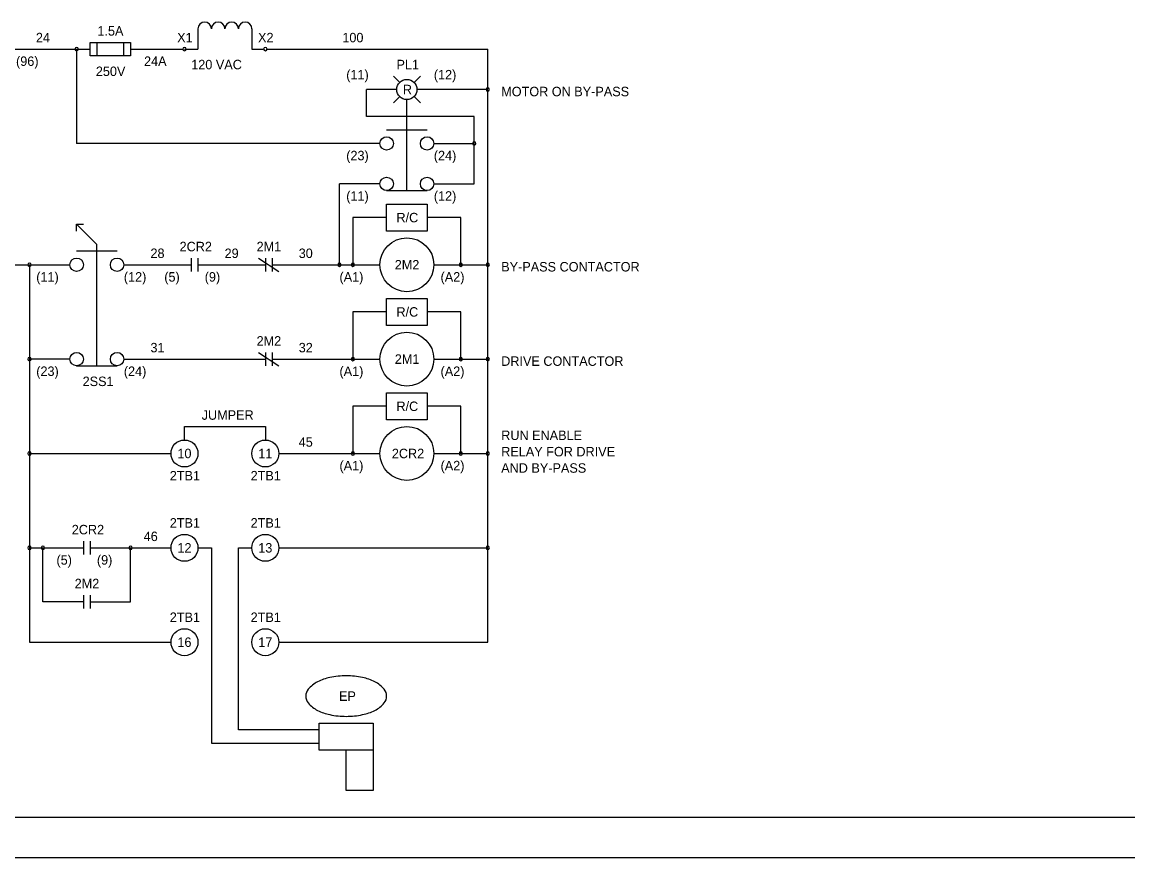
# Model space of a CAD drawing. Extents: x 10338 to 10578, y 10012 to 10165.
# Drawn here: x 10403.8 to 10481.8, y 10064.7 to 10123.6 of the extents above; entities that cross this region are included whole.
import ezdxf

# ---------------------------------------------------------------- set-up
doc = ezdxf.new("R2010")
doc.units = 0
for name, color, linetype in [('Level 61', 7, 'Continuous'), ('Level 62', 7, 'Continuous'), ('Level 63', 7, 'Continuous')]:
    doc.layers.add(name, color=color, linetype=linetype)

# ---------------------------------------------------------------- blocks, each defined once
blk = doc.blocks.new('PL0')
at = {"layer": 'Level 63'}
for p, q in [((-0.00552, 0.00552), (-0.01042, 0.01042)), ((0.00552, 0.00552), (0.01042, 0.01042)), ((-0.00552, -0.00552), (-0.01042, -0.01042)), ((0.00552, -0.00552), (0.01042, -0.01042))]:
    blk.add_line(p, q, dxfattribs=at)
blk.add_circle((0, 0), 0.00781, dxfattribs=at)
blk = doc.blocks.new('EL0')
at = {"layer": 'Level 63'}
for centre, radius, start, end in [((-0.01206, -0.00902), 0.02244, 116.56505, 140.36073), ((-0.00479, -0.02357), 0.0387, 101.70092, 116.56505), ((0, -0.04669), 0.06232, 90, 101.70092), ((0, -0.04669), 0.06232, 78.29908, 90), ((0.00479, -0.02357), 0.0387, 63.43495, 78.29908), ((0.01206, -0.00902), 0.02244, 39.63927, 63.43495), ((-0.02295, 0), 0.0083, 140.36073, 180), ((-0.02295, 0), 0.0083, 180, 219.63927), ((0.02295, 0), 0.0083, 0, 39.63927), ((0.02295, 0), 0.0083, 320.36073, 0), ((-0.01206, 0.00902), 0.02244, 219.63927, 243.43495), ((0.01206, 0.00902), 0.02244, 296.56505, 320.36073), ((-0.00479, 0.02357), 0.0387, 243.43495, 258.29908), ((0, 0.04669), 0.06232, 258.29908, 270), ((0, 0.04669), 0.06232, 270, 281.70092), ((0.00479, 0.02357), 0.0387, 281.70092, 296.56505)]:
    blk.add_arc(centre, radius, start, end, dxfattribs=at)

msp = doc.modelspace()

# ---------------------------------------------------------------- linework, layer by layer
at = {"layer": 'Level 61'}
for p, q in [((10409.092, 10122.19), (10409.092, 10121.24)), ((10410.992, 10121.24), (10410.992, 10122.19)), ((10402.917, 10121.715), (10408.617, 10121.715)), ((10407.667, 10121.715), (10407.667, 10115.065)), ((10411.467, 10121.715), (10415.148, 10121.715)), ((10421.086, 10121.715), (10436.642, 10121.715)), ((10436.642, 10079.915), (10436.642, 10121.715)), ((10430.229, 10118.865), (10428.092, 10118.865)), ((10428.092, 10116.965), (10428.092, 10118.865)), ((10436.642, 10118.865), (10431.654, 10118.865)), ((10430.942, 10111.74), (10430.942, 10118.153)), ((10435.692, 10116.965), (10428.092, 10116.965)), ((10435.692, 10112.215), (10435.692, 10116.965)), ((10429.042, 10115.065), (10407.667, 10115.065)), ((10432.842, 10115.065), (10435.692, 10115.065)), ((10426.192, 10106.515), (10426.192, 10112.215)), ((10429.042, 10112.215), (10426.192, 10112.215)), ((10432.842, 10112.215), (10435.692, 10112.215)), ((10427.142, 10109.84), (10427.142, 10106.515)), ((10429.517, 10109.84), (10427.142, 10109.84)), ((10434.742, 10109.84), (10432.367, 10109.84)), ((10434.742, 10106.515), (10434.742, 10109.84)), ((10409.092, 10099.39), (10409.092, 10107.94)), ((10400.542, 10106.515), (10407.192, 10106.515)), ((10404.342, 10106.515), (10404.342, 10079.915)), ((10410.992, 10106.515), (10415.742, 10106.515)), ((10416.217, 10106.515), (10420.967, 10106.515)), ((10420.492, 10106.99), (10421.917, 10106.04)), ((10421.442, 10106.515), (10429.042, 10106.515)), ((10432.842, 10106.515), (10436.642, 10106.515)), ((10427.142, 10103.19), (10427.142, 10099.865)), ((10429.517, 10103.19), (10427.142, 10103.19)), ((10434.742, 10103.19), (10432.367, 10103.19)), ((10434.742, 10099.865), (10434.742, 10103.19)), ((10420.492, 10100.34), (10421.917, 10099.39)), ((10407.192, 10099.865), (10404.342, 10099.865)), ((10410.992, 10099.865), (10420.967, 10099.865)), ((10421.442, 10099.865), (10429.042, 10099.865)), ((10432.842, 10099.865), (10436.642, 10099.865)), ((10427.142, 10096.54), (10427.142, 10093.215)), ((10429.517, 10096.54), (10427.142, 10096.54)), ((10434.742, 10096.54), (10432.367, 10096.54)), ((10434.742, 10093.215), (10434.742, 10096.54)), ((10404.342, 10093.215), (10414.317, 10093.215)), ((10421.917, 10093.215), (10429.042, 10093.215)), ((10432.842, 10093.215), (10436.642, 10093.215)), ((10404.342, 10086.565), (10408.142, 10086.565)), ((10405.292, 10082.765), (10405.292, 10086.565)), ((10408.617, 10086.565), (10414.317, 10086.565)), ((10411.467, 10082.765), (10411.467, 10086.565)), ((10416.217, 10086.565), (10417.167, 10086.565)), ((10417.167, 10086.565), (10417.167, 10072.79)), ((10419.067, 10073.74), (10419.067, 10086.565)), ((10419.067, 10086.565), (10420.017, 10086.565)), ((10421.917, 10086.565), (10436.642, 10086.565)), ((10408.142, 10082.765), (10405.292, 10082.765)), ((10408.617, 10082.765), (10411.467, 10082.765)), ((10404.342, 10079.915), (10414.317, 10079.915)), ((10421.917, 10079.915), (10436.642, 10079.915)), ((10424.767, 10073.74), (10419.067, 10073.74)), ((10417.167, 10072.79), (10424.767, 10072.79)), ((10521.192, 10067.565), (10376.317, 10067.565)), ((10524.042, 10064.715), (10373.467, 10064.715))]:
    msp.add_line(p, q, dxfattribs=at)
msp.add_lwpolyline([(10415.267, 10094.165), (10415.267, 10095.115), (10420.967, 10095.115), (10420.967, 10094.165)], dxfattribs=at)
for centre, start, end in [((10407.667, 10121.715), 0, 180), ((10407.667, 10121.715), 180, 0), ((10436.642, 10118.865), 0, 180), ((10436.642, 10118.865), 180, 0), ((10435.692, 10115.065), 0, 180), ((10435.692, 10115.065), 180, 0), ((10404.342, 10106.515), 0, 180), ((10404.342, 10106.515), 180, 0), ((10426.192, 10106.515), 0, 180), ((10426.192, 10106.515), 180, 0), ((10427.142, 10106.515), 0, 180), ((10427.142, 10106.515), 180, 0), ((10434.742, 10106.515), 0, 180), ((10434.742, 10106.515), 180, 0), ((10436.642, 10106.515), 0, 180), ((10436.642, 10106.515), 180, 0), ((10404.342, 10099.865), 0, 180), ((10404.342, 10099.865), 180, 0), ((10427.142, 10099.865), 0, 180), ((10427.142, 10099.865), 180, 0), ((10434.742, 10099.865), 0, 180), ((10434.742, 10099.865), 180, 0), ((10436.642, 10099.865), 0, 180), ((10436.642, 10099.865), 180, 0), ((10404.342, 10093.215), 0, 180), ((10404.342, 10093.215), 180, 0), ((10427.142, 10093.215), 0, 180), ((10427.142, 10093.215), 180, 0), ((10434.742, 10093.215), 0, 180), ((10434.742, 10093.215), 180, 0), ((10436.642, 10093.215), 0, 180), ((10436.642, 10093.215), 180, 0), ((10404.342, 10086.565), 0, 180), ((10404.342, 10086.565), 180, 0), ((10405.292, 10086.565), 0, 180), ((10405.292, 10086.565), 180, 0), ((10411.467, 10086.565), 0, 180), ((10411.467, 10086.565), 180, 0), ((10436.642, 10086.565), 0, 180), ((10436.642, 10086.565), 180, 0)]:
    msp.add_arc(centre, 0.119, start, end, dxfattribs=at)
at = {"layer": 'Level 62'}
for p, q in [((10416.217, 10123.14), (10416.217, 10121.715)), ((10420.017, 10123.14), (10420.017, 10121.715)), ((10415.267, 10121.715), (10416.217, 10121.715)), ((10420.017, 10121.715), (10420.808, 10121.715)), ((10429.517, 10116.015), (10432.367, 10116.015)), ((10429.517, 10111.74), (10432.367, 10111.74)), ((10409.092, 10107.94), (10407.667, 10109.365)), ((10407.667, 10108.89), (10407.667, 10109.365)), ((10407.667, 10109.365), (10408.142, 10109.365)), ((10410.517, 10107.465), (10407.667, 10107.465)), ((10415.742, 10106.99), (10415.742, 10106.04)), ((10416.217, 10106.99), (10416.217, 10106.04)), ((10420.967, 10106.99), (10420.967, 10106.04)), ((10421.442, 10106.99), (10421.442, 10106.04)), ((10420.967, 10100.34), (10420.967, 10099.39)), ((10421.442, 10100.34), (10421.442, 10099.39)), ((10407.667, 10099.39), (10410.517, 10099.39)), ((10408.142, 10087.04), (10408.142, 10086.09)), ((10408.617, 10087.04), (10408.617, 10086.09)), ((10408.142, 10083.24), (10408.142, 10082.29)), ((10408.617, 10083.24), (10408.617, 10082.29)), ((10424.767, 10072.315), (10424.767, 10074.215)), ((10424.767, 10074.215), (10428.567, 10074.215)), ((10428.567, 10074.215), (10428.567, 10069.465)), ((10428.567, 10072.315), (10424.767, 10072.315)), ((10426.667, 10069.465), (10426.667, 10072.315)), ((10428.567, 10069.465), (10426.667, 10069.465))]:
    msp.add_line(p, q, dxfattribs=at)
for points in [[(10408.617, 10122.19), (10411.467, 10122.19), (10411.467, 10121.24), (10408.617, 10121.24)], [(10429.517, 10110.79), (10432.367, 10110.79), (10432.367, 10108.89), (10429.517, 10108.89)], [(10429.517, 10104.14), (10432.367, 10104.14), (10432.367, 10102.24), (10429.517, 10102.24)], [(10429.517, 10097.49), (10432.367, 10097.49), (10432.367, 10095.59), (10429.517, 10095.59)]]:
    msp.add_lwpolyline(points, close=True, dxfattribs=at)
for centre, radius in [((10429.517, 10115.065), 0.475), ((10432.367, 10115.065), 0.475), ((10429.517, 10112.215), 0.475), ((10432.367, 10112.215), 0.475), ((10430.942, 10106.515), 1.9), ((10407.667, 10106.515), 0.475), ((10410.517, 10106.515), 0.475), ((10430.942, 10099.865), 1.9), ((10407.667, 10099.865), 0.475), ((10410.517, 10099.865), 0.475), ((10430.942, 10093.215), 1.9), ((10415.267, 10093.215), 0.95), ((10420.967, 10093.215), 0.95), ((10415.267, 10086.565), 0.95), ((10420.967, 10086.565), 0.95), ((10415.267, 10079.915), 0.95), ((10420.967, 10079.915), 0.95)]:
    msp.add_circle(centre, radius, dxfattribs=at)
for centre, radius, start, end in [((10416.692, 10123.14), 0.475, 0, 180), ((10417.642, 10123.14), 0.475, 0, 180), ((10418.592, 10123.14), 0.475, 0, 180), ((10419.542, 10123.14), 0.475, 0, 180), ((10415.267, 10121.715), 0.119, 0, 180), ((10415.267, 10121.715), 0.119, 180, 0), ((10420.967, 10121.715), 0.119, 0, 180), ((10420.967, 10121.715), 0.119, 180, 0)]:
    msp.add_arc(centre, radius, start, end, dxfattribs=at)

# ---------------------------------------------------------------- block references
at = {"layer": 'Level 62', "xscale": 91.19999999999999, "yscale": 91.2}
msp.add_blockref('PL0', (10430.943, 10118.866), dxfattribs=at)
at = {"layer": 'Level 63', "xscale": 91.19999999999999, "yscale": 91.2}
msp.add_blockref('EL0', (10426.668, 10076.116), dxfattribs=at)

# ---------------------------------------------------------------- texts
at = {"layer": 'Level 63'}
for s, height, p in [('24', 0.6667, (10404.794, 10122.191)), ('1.5A', 0.6667, (10409.129, 10122.666)), ('X1', 0.6667, (10414.752, 10122.191)), ('X2', 0.6667, (10420.453, 10122.191)), ('100', 0.6667, (10426.393, 10122.191)), ('(96)', 0.6667, (10403.393, 10120.528)), ('24A', 0.6667, (10412.418, 10120.528)), ('250V', 0.6667, (10409.019, 10119.816)), ('120 VAC', 0.6667, (10415.743, 10120.291)), ('PL1', 0.6667, (10430.212, 10120.291)), ('(11)', 0.6667, (10426.668, 10119.578)), ('(12)', 0.6667, (10432.843, 10119.578)), ('R', 0.667, (10430.659, 10118.532)), ('MOTOR ON BY-PASS', 0.66667, (10437.593, 10118.391)), ('(23)', 0.6667, (10426.668, 10113.878)), ('(24)', 0.6667, (10432.843, 10113.878)), ('(11)', 0.6667, (10426.668, 10111.028)), ('(12)', 0.6667, (10432.843, 10111.028)), ('R/C', 0.6667, (10430.208, 10109.507)), ('2CR2', 0.6667, (10414.922, 10107.466)), ('2M1', 0.6667, (10420.352, 10107.466)), ('28', 0.6667, (10412.869, 10106.991)), ('29', 0.6667, (10418.094, 10106.991)), ('30', 0.6667, (10423.318, 10106.991)), ('2M2', 0.6667, (10430.089, 10106.182)), ('BY-PASS CONTACTOR', 0.66667, (10437.593, 10106.041)), ('(11)', 0.6667, (10404.818, 10105.328)), ('(12)', 0.6667, (10410.993, 10105.328)), ('(5)', 0.6667, (10413.843, 10105.328)), ('(9)', 0.6667, (10416.693, 10105.328)), ('(A1)', 0.6667, (10426.193, 10105.328)), ('(A2)', 0.6667, (10433.318, 10105.328)), ('R/C', 0.6667, (10430.208, 10102.857)), ('31', 0.6667, (10412.868, 10100.341)), ('2M2', 0.6667, (10420.352, 10100.816)), ('32', 0.6667, (10423.319, 10100.341)), ('2M1', 0.6667, (10430.09, 10099.532)), ('(23)', 0.6667, (10404.818, 10098.678)), ('(24)', 0.6667, (10410.993, 10098.678)), ('(A1)', 0.6667, (10426.193, 10098.678)), ('(A2)', 0.6667, (10433.318, 10098.678)), ('DRIVE CONTACTOR', 0.66667, (10437.593, 10099.391)), ('2SS1', 0.6667, (10408.087, 10097.966)), ('JUMPER', 0.6667, (10416.479, 10095.591)), ('R/C', 0.6667, (10430.208, 10096.207)), ('RUN ENABLE', 0.6667, (10437.593, 10094.166)), ('45', 0.6667, (10423.319, 10093.691)), ('10', 0.6667, (10414.768, 10092.882)), ('11', 0.6667, (10420.468, 10092.882)), ('2CR2', 0.6667, (10429.884, 10092.882)), ('RELAY FOR DRIVE', 0.66667, (10437.593, 10093.012)), ('(A1)', 0.6667, (10426.193, 10092.028)), ('(A2)', 0.6667, (10433.318, 10092.028)), ('AND BY-PASS', 0.66667, (10437.593, 10091.858)), ('2TB1', 0.6667, (10414.23, 10091.316)), ('2TB1', 0.6667, (10419.93, 10091.316)), ('2TB1', 0.6667, (10414.23, 10087.991)), ('2TB1', 0.6667, (10419.93, 10087.991)), ('2CR2', 0.6667, (10407.322, 10087.516)), ('46', 0.6667, (10412.393, 10087.041)), ('12', 0.6667, (10414.769, 10086.232)), ('13', 0.6667, (10420.469, 10086.232)), ('(5)', 0.6667, (10406.243, 10085.378)), ('(9)', 0.6667, (10409.093, 10085.378)), ('2M2', 0.6667, (10407.527, 10083.716)), ('2TB1', 0.6667, (10414.23, 10081.341)), ('2TB1', 0.6667, (10419.93, 10081.341)), ('16', 0.6667, (10414.768, 10079.582)), ('17', 0.6667, (10420.469, 10079.582)), ('EP', 0.6667, (10426.158, 10075.782))]:
    msp.add_text(s, height=height, dxfattribs=at).set_placement(p)

doc.saveas('drawing.dxf')
